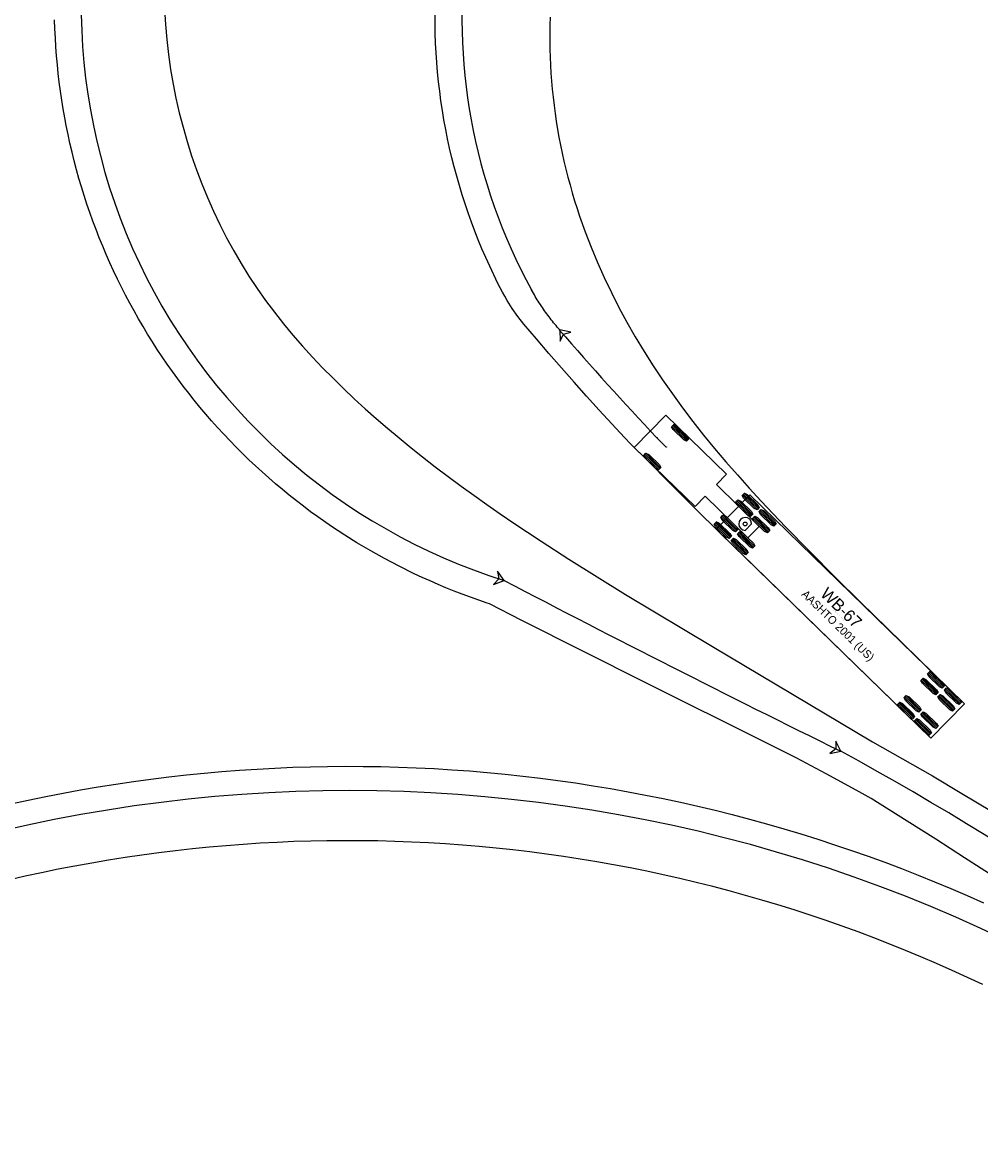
# Model space of a CAD drawing. Extents: x 2175591 to 2194071, y 76570 to 86955.
# Drawn here: x 2176550.3 to 2176719.9, y 77153.4 to 77349.1 of the extents above; entities that cross this region are included whole.
import ezdxf

# ---------------------------------------------------------------- set-up
doc = ezdxf.new("R2010")
doc.units = 0
doc.layers.add('C-UTIL-STRM-TEXT', color=7, linetype='Continuous')

msp = doc.modelspace()

# ---------------------------------------------------------------- linework, layer by layer
at = {"layer": 'C-UTIL-STRM-TEXT'}
for p, q in [((2176664.15, 77279.56), (2176658.57, 77273.83)), ((2176674.9, 77269.1), (2176664.15, 77279.56)), ((2176665.22, 77277.55), (2176667.85, 77275)), ((2176665.38, 77277.72), (2176668.01, 77275.16)), ((2176665.54, 77277.88), (2176668.17, 77275.33)), ((2176658.57, 77273.83), (2176669.32, 77263.36)), ((2176658.57, 77273.83), (2176658.57, 77273.83)), ((2176660.44, 77272.64), (2176663.07, 77270.09)), ((2176660.6, 77272.81), (2176663.23, 77270.25)), ((2176660.28, 77272.48), (2176662.91, 77269.92)), ((2176673.11, 77267.26), (2176674.9, 77269.1)), ((2176680.69, 77259.87), (2176673.11, 77267.26)), ((2176669.32, 77263.36), (2176671.11, 77265.2)), ((2176671.11, 77265.2), (2176678.69, 77257.82)), ((2176679.01, 77265.44), (2176673.09, 77259.35)), ((2176677.7, 77265.41), (2176680.33, 77262.85)), ((2176677.86, 77265.57), (2176680.49, 77263.01)), ((2176678.02, 77265.73), (2176680.65, 77263.18)), ((2176716.99, 77228.47), (2176679.01, 77265.44)), ((2176676.55, 77264.22), (2176679.18, 77261.67)), ((2176676.71, 77264.39), (2176679.34, 77261.83)), ((2176676.87, 77264.55), (2176679.5, 77261.99)), ((2176681.01, 77262.83), (2176683.64, 77260.27)), ((2176673.91, 77261.51), (2176676.54, 77258.95)), ((2176674.07, 77261.68), (2176676.7, 77259.12)), ((2176674.23, 77261.84), (2176676.86, 77259.28)), ((2176679.54, 77261.32), (2176682.17, 77258.76)), ((2176679.7, 77261.48), (2176682.33, 77258.92)), ((2176679.86, 77261.64), (2176682.49, 77259.09)), ((2176680.69, 77262.5), (2176683.32, 77259.94)), ((2176680.85, 77262.66), (2176683.48, 77260.11)), ((2176672.76, 77260.33), (2176675.39, 77257.77)), ((2176672.92, 77260.49), (2176675.55, 77257.94)), ((2176673.08, 77260.66), (2176675.71, 77258.1)), ((2176673.09, 77259.35), (2176711.06, 77222.38)), ((2176673.09, 77259.35), (2176673.09, 77259.35)), ((2176677.22, 77258.93), (2176679.85, 77256.38)), ((2176678.22, 77259.16), (2176679.34, 77260.32)), ((2176678.69, 77257.82), (2176680.69, 77259.87)), ((2176675.75, 77257.42), (2176678.38, 77254.87)), ((2176675.91, 77257.59), (2176678.54, 77255.03)), ((2176676.07, 77257.75), (2176678.7, 77255.19)), ((2176676.9, 77258.61), (2176679.53, 77256.05)), ((2176677.06, 77258.77), (2176679.69, 77256.21)), ((2176710.48, 77233.85), (2176713.11, 77231.29)), ((2176710.64, 77234.01), (2176713.27, 77231.45)), ((2176710.8, 77234.17), (2176713.43, 77231.62)), ((2176709.33, 77232.66), (2176711.96, 77230.11)), ((2176709.49, 77232.83), (2176712.12, 77230.27)), ((2176709.65, 77232.99), (2176712.28, 77230.43)), ((2176706.34, 77229.59), (2176708.97, 77227.04)), ((2176706.5, 77229.76), (2176709.13, 77227.2)), ((2176706.66, 77229.92), (2176709.29, 77227.36)), ((2176712.32, 77229.76), (2176714.94, 77227.2)), ((2176712.48, 77229.92), (2176715.1, 77227.36)), ((2176712.63, 77230.09), (2176715.26, 77227.53)), ((2176713.47, 77230.94), (2176716.09, 77228.38)), ((2176713.63, 77231.1), (2176716.25, 77228.55)), ((2176713.79, 77231.27), (2176716.41, 77228.71)), ((2176705.19, 77228.41), (2176707.82, 77225.85)), ((2176705.35, 77228.58), (2176707.98, 77226.02)), ((2176705.51, 77228.74), (2176708.14, 77226.18)), ((2176711.06, 77222.38), (2176716.99, 77228.47)), ((2176708.34, 77225.67), (2176710.96, 77223.11)), ((2176708.5, 77225.83), (2176711.12, 77223.28)), ((2176709.33, 77226.69), (2176711.95, 77224.13)), ((2176709.49, 77226.85), (2176712.11, 77224.29)), ((2176709.65, 77227.02), (2176712.27, 77224.46)), ((2176708.18, 77225.51), (2176710.8, 77222.95))]:
    msp.add_line(p, q, dxfattribs=at)
for points in [[(2176575.45, 77351.36), (2176575.62, 77348.69), (2176575.86, 77346.03), (2176576.17, 77343.38), (2176576.56, 77340.72), (2176577.01, 77338.1), (2176577.5, 77335.65), (2176578.09, 77333.06), (2176578.75, 77330.5), (2176579.47, 77327.97), (2176580.27, 77325.45), (2176581.13, 77322.96), (2176582.07, 77320.5), (2176583.06, 77318.06), (2176584.13, 77315.66), (2176585.26, 77313.29), (2176586.45, 77310.95), (2176587.71, 77308.65), (2176589.03, 77306.39), (2176590.41, 77304.17), (2176591.85, 77301.99), (2176593.36, 77299.85), (2176594.91, 77297.75), (2176596.53, 77295.71), (2176598.19, 77293.7), (2176599.9, 77291.74), (2176601.66, 77289.81), (2176603.45, 77287.92), (2176605.28, 77286.07), (2176607.14, 77284.25), (2176609.03, 77282.46), (2176610.96, 77280.7), (2176612.91, 77278.97), (2176614.9, 77277.26), (2176616.99, 77275.51), (2176619.12, 77273.77), (2176621.13, 77272.17), (2176623.38, 77270.42), (2176625.68, 77268.68), (2176627.95, 77267), (2176630.17, 77265.39), (2176632.5, 77263.73), (2176634.87, 77262.09), (2176637.25, 77260.46), (2176639.66, 77258.84), (2176642.09, 77257.23), (2176647.01, 77254.06), (2176652, 77250.92), (2176657.05, 77247.82), (2176662.13, 77244.74), (2176672.39, 77238.6), (2176700.75, 77221.72), (2176706.04, 77218.74), (2176711.31, 77215.7), (2176716.55, 77212.6), (2176721.75, 77209.45)], [(2176722.04, 77197.94), (2176717.01, 77201.24), (2176711.95, 77204.5), (2176706.87, 77207.73), (2176700.49, 77211.73), (2176697.85, 77213.19), (2176692.55, 77216.07), (2176687.21, 77218.88), (2176681.92, 77221.59), (2176660.5, 77232.23), (2176649.59, 77237.7), (2176638.71, 77243.21), (2176632.94, 77246.15), (2176632.58, 77246.3), (2176631.09, 77246.8), (2176629.62, 77247.33), (2176628.15, 77247.87), (2176626.7, 77248.43), (2176625.27, 77249), (2176623.86, 77249.59), (2176622.44, 77250.21), (2176621.04, 77250.84), (2176619.64, 77251.49), (2176616.99, 77252.8), (2176614.38, 77254.17), (2176611.96, 77255.52), (2176609.52, 77256.97), (2176607.35, 77258.33), (2176605, 77259.87), (2176602.61, 77261.54), (2176601.32, 77262.47), (2176600.05, 77263.42), (2176598.8, 77264.39), (2176597.55, 77265.38), (2176596.33, 77266.39), (2176595.11, 77267.41), (2176593.91, 77268.45), (2176592.73, 77269.5), (2176591.56, 77270.58), (2176590.4, 77271.67), (2176589.26, 77272.78), (2176588.14, 77273.9), (2176587.03, 77275.04), (2176585.94, 77276.19), (2176584.87, 77277.36), (2176583.81, 77278.55), (2176582.77, 77279.75), (2176581.74, 77280.96), (2176580.74, 77282.19), (2176579.75, 77283.44), (2176578.78, 77284.7), (2176577.82, 77285.97), (2176576.89, 77287.25), (2176575.97, 77288.55), (2176575.07, 77289.86), (2176574.19, 77291.19), (2176573.33, 77292.53), (2176572.49, 77293.88), (2176571.67, 77295.24), (2176570.86, 77296.61), (2176570.08, 77297.99), (2176569.32, 77299.39), (2176568.57, 77300.8), (2176567.85, 77302.21), (2176567.15, 77303.64), (2176566.46, 77305.08), (2176565.8, 77306.52), (2176565.16, 77307.98), (2176564.54, 77309.44), (2176563.94, 77310.92), (2176563.36, 77312.4), (2176562.8, 77313.89), (2176562.27, 77315.39), (2176561.75, 77316.89), (2176561.26, 77318.41), (2176560.79, 77319.93), (2176560.34, 77321.45), (2176559.91, 77322.99), (2176559.49, 77324.56), (2176559.11, 77326.12), (2176558.74, 77327.67), (2176558.4, 77329.23), (2176558.09, 77330.79), (2176557.82, 77332.18), (2176557.55, 77333.75), (2176557.29, 77335.32), (2176557.06, 77336.9), (2176556.86, 77338.48), (2176556.68, 77340.02), (2176556.52, 77341.57), (2176556.37, 77343.15), (2176556.26, 77344.74), (2176556.16, 77346.33), (2176556.09, 77347.92), (2176556.04, 77349.51)], [(2176710.97, 77222.47), (2176673.85, 77258.6), (2176669.22, 77263.14), (2176666.92, 77265.43), (2176664.64, 77267.74), (2176661.22, 77271.24), (2176657.99, 77274.4), (2176656.85, 77275.59), (2176654.61, 77278), (2176652.38, 77280.43), (2176650.15, 77282.89), (2176647.93, 77285.38), (2176645.71, 77287.9), (2176643.49, 77290.45), (2176641.26, 77293.04), (2176639.04, 77295.67), (2176637.99, 77297.03), (2176637, 77298.43), (2176636.09, 77299.86), (2176635.66, 77300.59), (2176635.24, 77301.33), (2176634.46, 77302.84), (2176633.72, 77304.36), (2176633, 77305.89), (2176632.3, 77307.44), (2176631.63, 77308.99), (2176630.98, 77310.56), (2176630.36, 77312.14), (2176629.76, 77313.73), (2176629.19, 77315.33), (2176628.64, 77316.94), (2176628.12, 77318.56), (2176627.63, 77320.19), (2176627.16, 77321.82), (2176626.72, 77323.47), (2176626.3, 77325.12), (2176625.91, 77326.78), (2176625.55, 77328.45), (2176625.22, 77330.12), (2176624.91, 77331.8), (2176624.63, 77333.48), (2176624.38, 77335.17), (2176624.15, 77336.86), (2176623.95, 77338.56), (2176623.78, 77340.26), (2176623.64, 77341.96), (2176623.52, 77343.67), (2176623.43, 77345.38), (2176623.37, 77347.09), (2176623.34, 77348.8), (2176623.34, 77350.51)], [(2176643.71, 77349.99), (2176643.66, 77348.57), (2176643.64, 77347.16), (2176643.63, 77345.74), (2176643.65, 77344.32), (2176643.69, 77342.9), (2176643.75, 77341.48), (2176643.83, 77340.06), (2176643.94, 77338.64), (2176644.06, 77337.22), (2176644.21, 77335.8), (2176644.38, 77334.38), (2176644.56, 77332.96), (2176644.77, 77331.55), (2176645.01, 77330.13), (2176645.26, 77328.72), (2176645.53, 77327.31), (2176645.83, 77325.9), (2176646.14, 77324.49), (2176646.48, 77323.09), (2176646.83, 77321.69), (2176647.21, 77320.3), (2176647.6, 77318.9), (2176648.02, 77317.51), (2176648.46, 77316.13), (2176648.91, 77314.75), (2176649.88, 77312), (2176650.93, 77309.28), (2176652.06, 77306.57), (2176653.26, 77303.89), (2176654.53, 77301.23), (2176655.87, 77298.59), (2176657.28, 77295.98), (2176658.76, 77293.4), (2176660.31, 77290.84), (2176661.92, 77288.31), (2176663.59, 77285.8), (2176665.32, 77283.32), (2176667.11, 77280.87), (2176668.95, 77278.44), (2176670.85, 77276.04), (2176672.79, 77273.66), (2176674.79, 77271.31), (2176676.82, 77268.97), (2176678.9, 77266.66), (2176681.01, 77264.36), (2176683.16, 77262.07), (2176685.35, 77259.78), (2176689.61, 77255.43), (2176694.13, 77250.89), (2176698.68, 77246.37), (2176703.29, 77241.83), (2176716.99, 77228.47), (2176711.06, 77222.38), (2176710.97, 77222.47), (2176710.97, 77222.47)], [(2176645.38, 77294.63), (2176645.17, 77294.88), (2176644.95, 77295.14), (2176644.74, 77295.39), (2176644.52, 77295.65), (2176644.31, 77295.91), (2176644.11, 77296.17), (2176643.9, 77296.43), (2176643.7, 77296.69), (2176643.5, 77296.96), (2176643.3, 77297.23), (2176643.1, 77297.49), (2176642.9, 77297.76), (2176642.71, 77298.04), (2176642.52, 77298.31), (2176642.33, 77298.58), (2176642.14, 77298.86), (2176641.96, 77299.14), (2176641.78, 77299.42), (2176641.6, 77299.7), (2176641.42, 77299.98), (2176641.25, 77300.27), (2176641.07, 77300.55), (2176640.91, 77300.84), (2176640.74, 77301.13), (2176640.58, 77301.42), (2176640.41, 77301.71)], [(2176664.23, 77273.9), (2176663.99, 77274.13), (2176663.75, 77274.37), (2176663.52, 77274.6), (2176663.28, 77274.84), (2176663.05, 77275.08), (2176662.82, 77275.32), (2176662.59, 77275.56)], [(2176548.29, 77210.75), (2176551.37, 77211.43), (2176554.45, 77212.07), (2176557.54, 77212.67), (2176560.64, 77213.24), (2176563.74, 77213.77), (2176566.85, 77214.26), (2176569.96, 77214.72), (2176573.08, 77215.15), (2176576.21, 77215.53), (2176579.34, 77215.88), (2176582.47, 77216.2), (2176585.61, 77216.48), (2176588.74, 77216.72), (2176591.89, 77216.93), (2176595.01, 77217.1), (2176598.16, 77217.23), (2176601.31, 77217.33), (2176604.28, 77217.39), (2176607.43, 77217.41), (2176610.59, 77217.4), (2176613.73, 77217.36), (2176616.88, 77217.27), (2176620.02, 77217.16), (2176623.16, 77217), (2176626.3, 77216.81), (2176629.44, 77216.58), (2176632.58, 77216.32), (2176635.71, 77216.02), (2176638.84, 77215.68), (2176641.96, 77215.31), (2176645.08, 77214.9), (2176648.19, 77214.46), (2176651.3, 77213.98), (2176654.4, 77213.46), (2176657.5, 77212.91), (2176660.59, 77212.33), (2176663.67, 77211.7), (2176666.75, 77211.05), (2176669.81, 77210.35), (2176672.87, 77209.62), (2176675.92, 77208.86), (2176678.96, 77208.06), (2176681.99, 77207.23), (2176685.02, 77206.36), (2176688.03, 77205.45), (2176691.03, 77204.51), (2176694.02, 77203.54), (2176696.99, 77202.53), (2176699.96, 77201.49), (2176702.91, 77200.42), (2176705.85, 77199.31), (2176708.78, 77198.16), (2176711.7, 77196.99), (2176714.6, 77195.78), (2176717.48, 77194.53), (2176720.35, 77193.26)], [(2176720.23, 77178.8), (2176717.51, 77180.06), (2176714.79, 77181.3), (2176712.05, 77182.5), (2176709.3, 77183.69), (2176706.53, 77184.84), (2176703.76, 77185.96), (2176700.97, 77187.04), (2176698.17, 77188.1), (2176695.35, 77189.12), (2176692.53, 77190.11), (2176689.69, 77191.07), (2176686.84, 77192), (2176683.98, 77192.89), (2176681.12, 77193.75), (2176678.24, 77194.57), (2176675.35, 77195.37), (2176672.45, 77196.13), (2176669.55, 77196.85), (2176666.63, 77197.55), (2176663.71, 77198.21), (2176660.78, 77198.83), (2176657.84, 77199.42), (2176654.9, 77199.98), (2176651.95, 77200.5), (2176648.99, 77200.99), (2176646.03, 77201.45), (2176643.07, 77201.87), (2176640.09, 77202.26), (2176637.12, 77202.61), (2176634.14, 77202.93), (2176631.16, 77203.21), (2176628.17, 77203.46), (2176625.18, 77203.68), (2176622.19, 77203.86), (2176619.19, 77204.01), (2176616.2, 77204.12), (2176613.2, 77204.2), (2176610.2, 77204.24), (2176607.21, 77204.25), (2176604.21, 77204.23), (2176601.38, 77204.17), (2176598.38, 77204.08), (2176595.38, 77203.95), (2176592.38, 77203.79), (2176589.39, 77203.59), (2176586.39, 77203.36), (2176583.4, 77203.1), (2176580.42, 77202.8), (2176577.43, 77202.47), (2176574.46, 77202.1), (2176571.48, 77201.7), (2176568.51, 77201.26), (2176565.55, 77200.79), (2176562.59, 77200.29), (2176559.63, 77199.76), (2176556.68, 77199.19), (2176553.74, 77198.58), (2176550.81, 77197.94), (2176547.88, 77197.27)]]:
    msp.add_lwpolyline(points, dxfattribs=at)
for points in [[(2176645.38, 77294.63), (2176645.49, 77292.63), (2176646.03, 77293.87), (2176647.34, 77294.22)], [(2176665.18, 77277.51), (2176665.58, 77277.92), (2176666.07, 77277.69), (2176667.96, 77275.85), (2176668.21, 77275.37), (2176667.81, 77274.96), (2176667.32, 77275.19), (2176665.43, 77277.03)], [(2176660.24, 77272.44), (2176660.64, 77272.85), (2176661.13, 77272.61), (2176663.02, 77270.77), (2176663.27, 77270.29), (2176662.87, 77269.88), (2176662.38, 77270.12), (2176660.49, 77271.96)], [(2176677.66, 77265.36), (2176678.06, 77265.77), (2176678.55, 77265.54), (2176680.44, 77263.7), (2176680.69, 77263.22), (2176680.29, 77262.81), (2176679.8, 77263.04), (2176677.91, 77264.88)], [(2176676.51, 77264.18), (2176676.91, 77264.59), (2176677.4, 77264.36), (2176679.29, 77262.52), (2176679.54, 77262.03), (2176679.14, 77261.62), (2176678.65, 77261.86), (2176676.76, 77263.7)], [(2176680.65, 77262.46), (2176681.05, 77262.87), (2176681.54, 77262.63), (2176683.43, 77260.79), (2176683.68, 77260.31), (2176683.28, 77259.9), (2176682.79, 77260.13), (2176680.9, 77261.98)], [(2176673.87, 77261.47), (2176674.27, 77261.88), (2176674.76, 77261.65), (2176676.65, 77259.81), (2176676.9, 77259.32), (2176676.5, 77258.91), (2176676.01, 77259.15), (2176674.12, 77260.99)], [(2176679.5, 77261.28), (2176679.9, 77261.69), (2176680.39, 77261.45), (2176682.28, 77259.61), (2176682.53, 77259.13), (2176682.13, 77258.72), (2176681.64, 77258.95), (2176679.75, 77260.79)], [(2176672.72, 77260.29), (2176673.12, 77260.7), (2176673.61, 77260.46), (2176675.5, 77258.62), (2176675.75, 77258.14), (2176675.35, 77257.73), (2176674.86, 77257.97), (2176672.97, 77259.81)], [(2176676.86, 77258.56), (2176677.26, 77258.97), (2176677.75, 77258.74), (2176679.64, 77256.9), (2176679.89, 77256.42), (2176679.49, 77256.01), (2176679, 77256.24), (2176677.11, 77258.08)], [(2176675.71, 77257.38), (2176676.11, 77257.79), (2176676.6, 77257.56), (2176678.49, 77255.72), (2176678.74, 77255.23), (2176678.34, 77254.82), (2176677.85, 77255.06), (2176675.96, 77256.9)], [(2176635.56, 77250.29), (2176634.41, 77251.93), (2176634.61, 77250.59), (2176633.68, 77249.61)], [(2176710.44, 77233.8), (2176710.84, 77234.21), (2176711.33, 77233.98), (2176713.22, 77232.14), (2176713.47, 77231.66), (2176713.07, 77231.25), (2176712.58, 77231.48), (2176710.69, 77233.32)], [(2176709.29, 77232.62), (2176709.69, 77233.03), (2176710.18, 77232.8), (2176712.07, 77230.96), (2176712.32, 77230.47), (2176711.92, 77230.06), (2176711.43, 77230.3), (2176709.54, 77232.14)], [(2176706.3, 77229.55), (2176706.7, 77229.96), (2176707.19, 77229.73), (2176709.08, 77227.89), (2176709.33, 77227.41), (2176708.93, 77227), (2176708.44, 77227.23), (2176706.55, 77229.07)], [(2176712.28, 77229.72), (2176712.67, 77230.13), (2176713.16, 77229.89), (2176715.05, 77228.05), (2176715.3, 77227.57), (2176714.9, 77227.16), (2176714.41, 77227.39), (2176712.52, 77229.23)], [(2176713.43, 77230.9), (2176713.83, 77231.31), (2176714.31, 77231.07), (2176716.21, 77229.23), (2176716.45, 77228.75), (2176716.05, 77228.34), (2176715.57, 77228.58), (2176713.67, 77230.42)], [(2176705.15, 77228.37), (2176705.55, 77228.78), (2176706.04, 77228.55), (2176707.93, 77226.7), (2176708.18, 77226.22), (2176707.78, 77225.81), (2176707.29, 77226.05), (2176705.4, 77227.89)], [(2176708.14, 77225.46), (2176708.54, 77225.87), (2176709.02, 77225.64), (2176710.92, 77223.8), (2176711.16, 77223.32), (2176710.76, 77222.91), (2176710.28, 77223.14), (2176708.38, 77224.98)], [(2176709.29, 77226.65), (2176709.69, 77227.06), (2176710.17, 77226.82), (2176712.07, 77224.98), (2176712.31, 77224.5), (2176711.92, 77224.09), (2176711.43, 77224.32), (2176709.54, 77226.17)], [(2176695.13, 77220.08), (2176694.24, 77221.87), (2176694.23, 77220.52), (2176693.17, 77219.68)]]:
    msp.add_lwpolyline(points, close=True, dxfattribs=at)
for centre, radius in [((2176640.41, 77301.71), 0.0417), ((2176640.41, 77301.71), 0.0417), ((2176645.38, 77294.63), 0.0417), ((2176645.38, 77294.63), 0.0417), ((2176662.59, 77275.56), 0.0417), ((2176662.59, 77275.56), 0.0417), ((2176664.23, 77273.9), 0.0417), ((2176678.2, 77260.3), 0.34), ((2176635.56, 77250.29), 0.0417), ((2176635.56, 77250.29), 0.0417), ((2176695.13, 77220.08), 0.0417), ((2176695.13, 77220.08), 0.0417)]:
    msp.add_circle(centre, radius, dxfattribs=at)
for centre, radius, start, end in [((2176728.55, 77349.93), 100.47, 136.3071, 208.6816), ((2176667.58, 77352.25), 106.86, 155.1079, 252.5646), ((2177038.6, 77632.18), 518.24, 220.644, 223.4836), ((2176678.2, 77260.3), 1.14, 0.7688, 270.7688), ((2177867.95, 79605.77), 2658.39, 242.38136, 243.82097), ((2176430.53, 76735.3), 552.28, 49.2072, 61.3738), ((2176608.17, 76944.87), 268.23, 53.8493, 119.9853)]:
    msp.add_arc(centre, radius, start, end, dxfattribs=at)

# ---------------------------------------------------------------- texts
for s, height, p in [('WB-67', 2.125, (2176691.35, 77247.73)), ('AASHTO 2001 (US)', 1.4167, (2176688.06, 77247.73)), ('(c) 2019 Transoft Solutions, Inc. All rights reserved.', 0.085, (2176693.77, 77245.09))]:
    msp.add_text(s, height=height, rotation=315.7688, dxfattribs=at).set_placement(p)

doc.saveas('drawing.dxf')
